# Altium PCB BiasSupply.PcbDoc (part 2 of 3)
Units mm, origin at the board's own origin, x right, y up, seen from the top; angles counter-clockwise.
Board outline 39 x 40.5 mm, 4 copper layers (Top Layer, Layer 2, Layer3, Bottom Layer), stack 0.661 mm thick; 168 components, 80 nets, 408 pads, 115 vias.
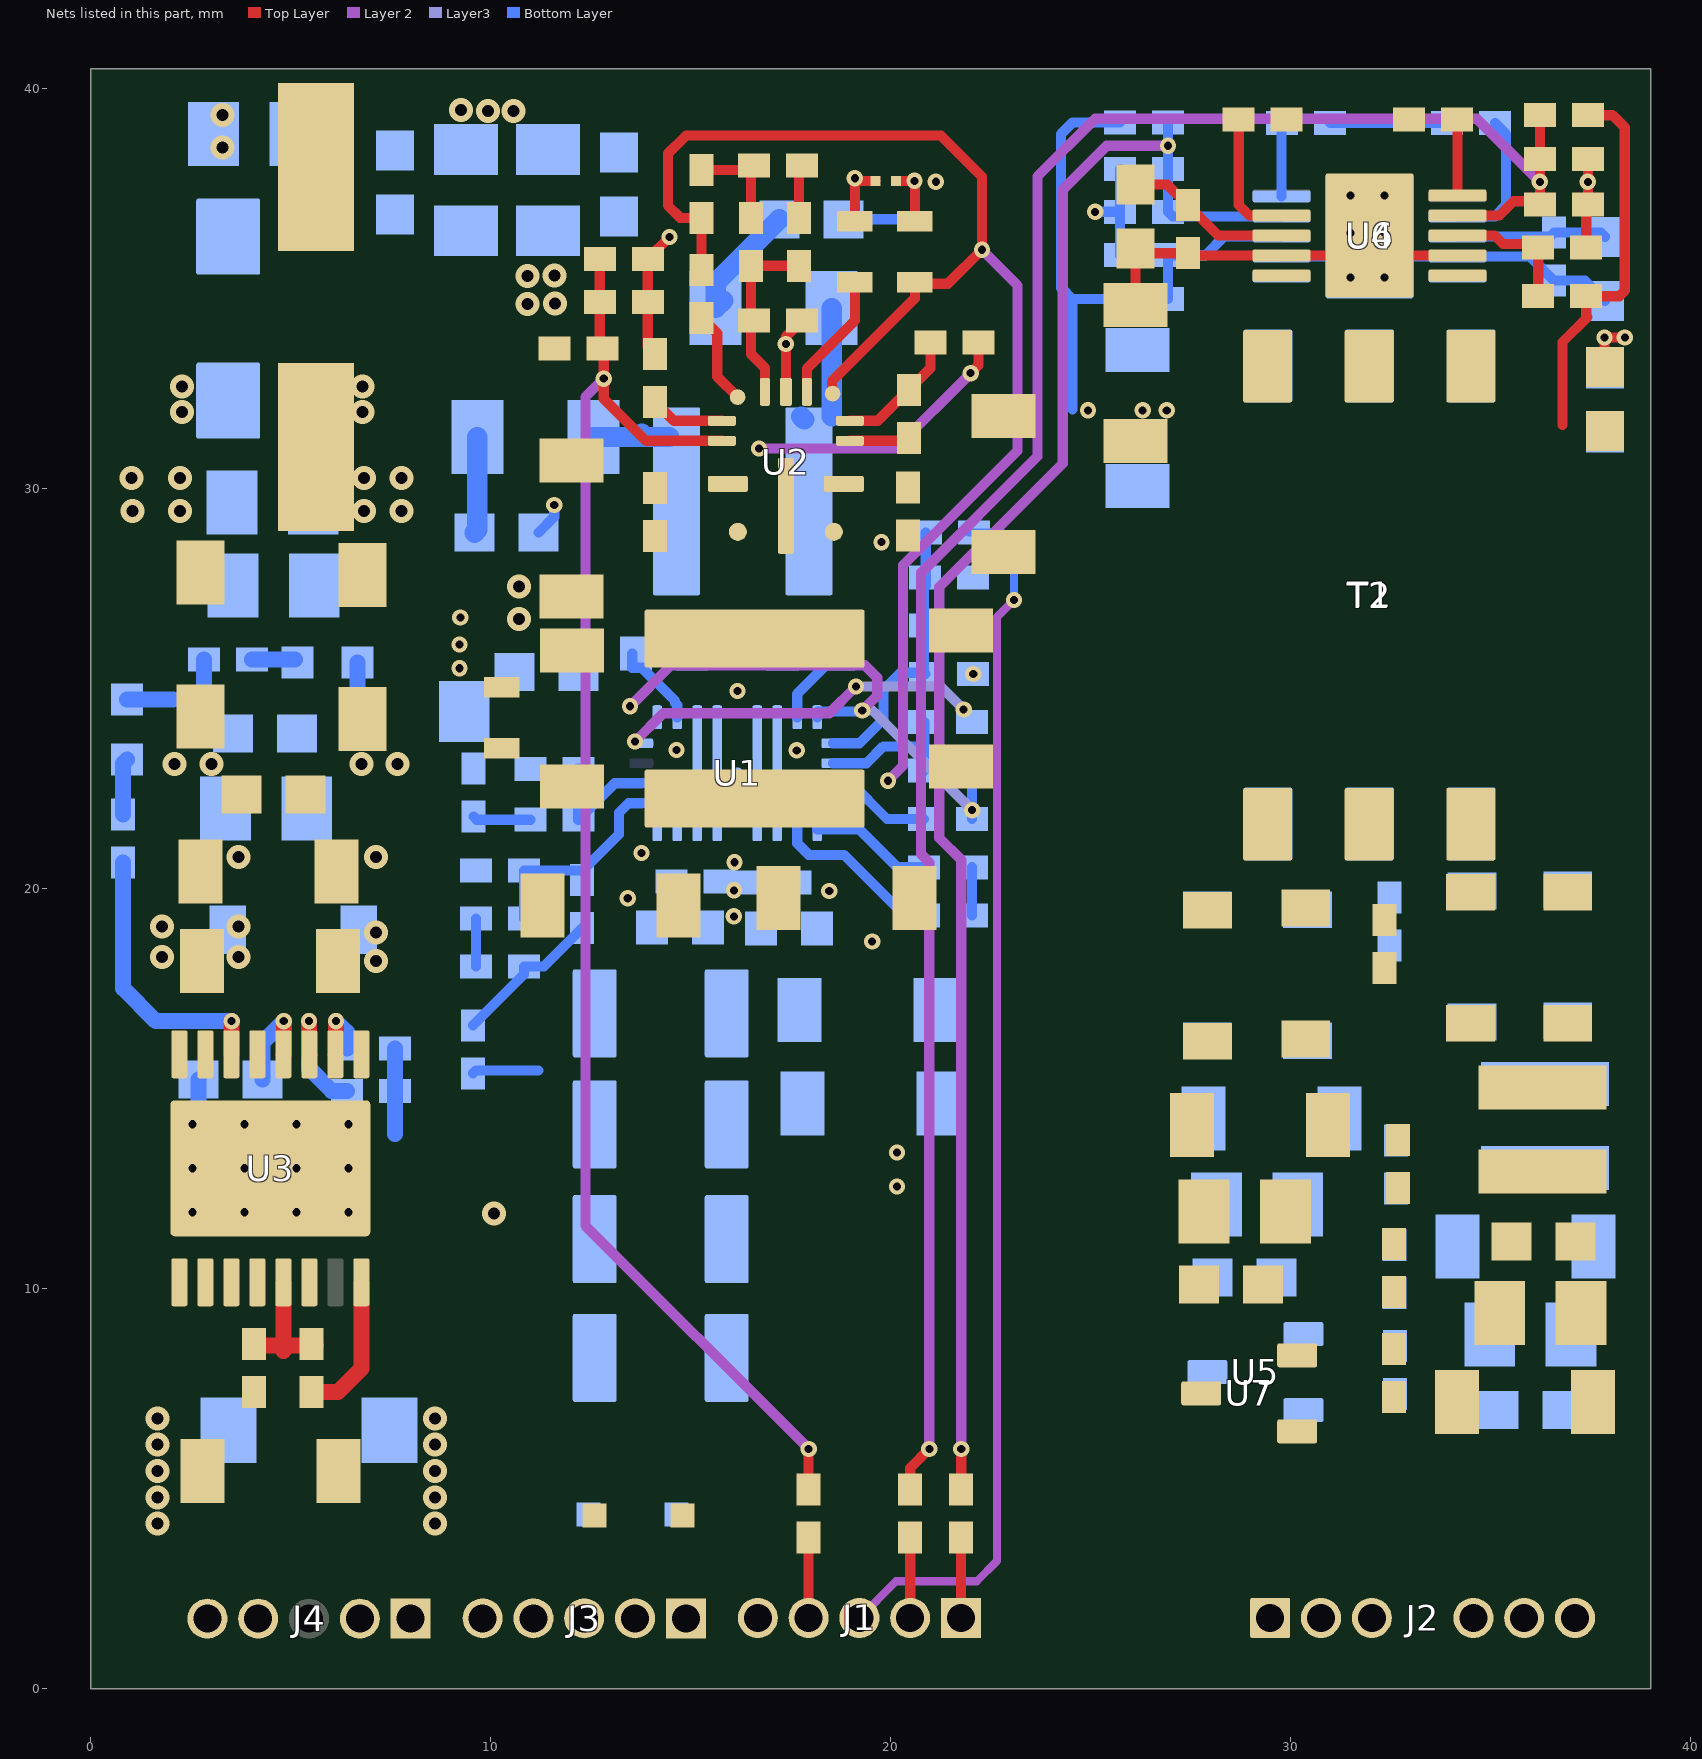
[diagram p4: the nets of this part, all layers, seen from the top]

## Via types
v1: diameter 0.406, hole 0.203, Top Layer to Bottom Layer, 57 vias
v2: diameter 0.6, hole 0.3, Top Layer to Bottom Layer, 46 vias
v3: diameter 0.5, hole 0.203, Top Layer to Bottom Layer, 6 vias
v4: diameter 0.5, hole 0.203, Top Layer to Bottom Layer, tented both sides, 6 vias

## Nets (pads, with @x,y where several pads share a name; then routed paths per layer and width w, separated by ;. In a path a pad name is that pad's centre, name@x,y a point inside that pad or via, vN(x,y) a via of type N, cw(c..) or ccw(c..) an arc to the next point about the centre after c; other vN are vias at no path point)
AGND1: C37.2 C48.2 NT2.2 R13.1 R17.1 R18.1 U2.3 | length 6.8
  Top Layer w0.254: R18.1@14.104,33.371 13.928,33.548 R17.1@13.928,34.671 C37.2@13.928,35.745 14.47,36.287 v1(14.47,36.295) ; U2.3@17.379,32.421 v1(17.379,33.615) 17.379,33.801 R13.1@17.784,34.206 ; C48.2@19.104,36.721 v1(19.104,37.759) 19.168,37.696 NT2.2@19.621,37.696
AGND2: C23.2 C24.2 C25.2 C59.2 NT1.1 R9.1 R11.1 R12.1 R26.1 U1.17 | length 10.2
  Layer 2 w0.254: v1(13.609,23.677) 14.317,24.386 18.467,24.386 v1(19.135,25.054)
  Layer3 w0.254: v1(19.135,25.054) 21.249,25.054 v1(21.825,24.478)
  Bottom Layer w0.254: R9.1@22.037,19.328 C24.2@22.037,20.535
BIAS_5V: C39.1 C40.2 C41.2 C47.1 C65.2 C66.2 D15.1 J3.1 L3.2 R19.1 R20.2 U2.1 | length 34.4
  Top Layer w0.254: R19.1@15.275,35.471 R20.2@15.275,36.771 14.74,36.771 14.43,37.081 14.43,38.373 14.882,38.825 21.257,38.825 22.282,37.8 v1(22.282,35.973) 21.43,35.121 20.604,35.121 20.604,34.759 18.529,32.684 U2.1@18.529,32.421
  Layer 2 w0.254: v1(19.935,22.698) 20.309,23.072 20.309,28.085 23.172,30.948 23.172,35.082 v1(22.282,35.973)
BIAS_12V: C13.1 C17.1 C18.1 C19.1 C20.1 C21.2 D1.1 J3.5 R3.2 U1.11 U1.12 U1.13 | length 1.7
  Bottom Layer w0.254: R3.2@9.559,15.385 9.632,15.458 11.198,15.458
  other v1: 13.427,19.76 13.771,20.891 14.646,23.469
BIAS_ISO_12V_1: C56.1 C57.1 C58.1 J2.3 L6.2 R36.2
BIAS_ISO_12V_2: C70.1 C71.1 C72.1 J2.7 L7.2 R49.2
BIAS_ISO_-5V_1: C44.2 C45.2 C67.2 D8.2 D9.2 J2.1 R46.1 U5.3
BIAS_ISO_-5V_2: C79.2 C80.2 C81.2 D12.2 D13.2 J2.5 R59.1 U7.3
BIAS_ISO_GND1: C44.1 C45.1 C56.2 C57.2 C58.2 C67.1 J2.2 R36.1 R37.2 R41.2 U5.1
BIAS_ISO_GND2: C70.2 C71.2 C72.2 C79.1 C80.1 C81.1 J2.6 R43.2 R49.1 R54.2 U7.1
BIAS_VIN: C3.1 C5.1 C6.2 C8.1 C15.1 C27.1 C28.1 C29.1 C30.1 C33.1 C34.1 C35.1 C36.1 C43.1 C64.1 C78.1 L2.2 R4.2 R14.2 R15.2 R35.2 R40.2 R45.2 R48.2 T1.2 T2.2 U1.7 U2.8 U2.12 | length 19.4
  Top Layer w0.254: 36.798,31.596 36.798,33.666 37.423,34.291 37.388,34.326 R40.2@37.388,34.812 38.214,34.812 38.354,34.952 38.354,39.032 38.049,39.337 R48.2@37.43,39.337
  Bottom Layer w0.254: 24.546,31.987 24.546,34.74 ; R35.2@25.732,34.74 24.546,34.74 ; R45.2@25.732,39.157 24.549,39.157 24.262,38.87 24.262,35.024 24.546,34.74
  other v1: 20.156,12.554 20.156,13.402 19.538,18.681 18.466,19.94 17.651,23.458 22.064,25.367 24.935,31.958 26.299,31.958 26.902,31.958
  other v2: 9.93,39.446 10.571,39.446 9.263,39.471
BIAS_VIN_EMI: C38.1 C51.1 C52.1 C53.1 C55.1 D2.1 D4.1 FB1.1 R27.2 U3.15 U3.16 | length 2.2
  Bottom Layer w0.4: D2.1@0.904,24.726 2.063,24.726 ; 2.832,24.698 R27.2@2.832,25.725
  other v2: 1.778,18.295 3.693,18.295 1.778,19.05 3.693,19.05 3.693,20.798 2.098,23.114 3.023,23.114
CBOOT_PIN: C46.1 R16.1 U2.14 | length 3.2
  Top Layer w0.254: U2.14@18.979,31.696 19.678,31.696 R16.1@20.453,32.471 20.993,33.011 C46.1@20.993,33.652
FB: C49.2 R13.2 R21.1 U2.4 | length 4.5
  Top Layer w0.254: U2.4@16.854,32.421 16.854,33.02 16.504,33.37 16.504,34.171 16.504,35.566 R21.1@16.509,35.571 C49.2@17.704,35.571
LM61440_EN: J1.4 R22.1 | length 2
  Top Layer w0.254: J1.4@17.949,1.768 R22.1@17.949,3.779
NetC1_1: C1.1 R1.2 | length 3.1
  Bottom Layer w0.508: R1.2@15.811,34.704 R1.2@15.625,34.519 15.625,35.142 C1.1@17.218,36.735
NetC2_1: C2.1 R2.1 | length 2.4
  Bottom Layer w0.508: C2.1@9.596,28.902 9.667,28.974 R2.1@9.667,31.294
NetC4_1: C4.1 R53.2 U4.8 | length 3.8
  Bottom Layer w0.254: U4.8@34.173,36.308 36.491,36.308 R53.2@36.583,36.4 37.751,36.4 C4.1@37.854,36.297
NetC7_1: C7.1 R68.2 U6.8 | length 4.2
  Top Layer w0.254: C7.1@26.124,37.601 26.917,37.601 R68.2@27.432,37.086 28.188,36.33 U6.8@29.773,36.33
NetC9_2: C9.2 R35.1 U4.3 | length 4.1
  Bottom Layer w0.254: R35.1@26.932,34.74 C9.2@26.932,35.837 27.871,35.837 28.341,36.308 U4.3@29.773,36.308
NetC10_1: C10.1 L1.1 R1.1 U1.8 | length 2.8
  Bottom Layer w0.508: L1.1@17.763,31.802 L1.1@17.838,31.728 ; L1.1@18.525,31.802 R1.1@18.525,34.519
NetC10_2: C10.2 U1.20 | length 2
  Bottom Layer w0.254: U1.20@17.665,24.286 17.665,24.871 C10.2@18.679,25.885
NetC12_1: C12.1 L1.2 R2.2 U1.10 | length 2
  Bottom Layer w0.508: R2.2@12.567,31.294 13.699,31.294 ; 13.78,31.375 13.699,31.294 ; L1.2@14.461,31.294 13.699,31.294
NetC12_2: C12.2 U1.19 | length 2.2
  Bottom Layer w0.254: C12.2@13.538,25.878 13.538,25.524 13.78,25.524 14.612,24.692 14.612,24.639 14.665,24.586 U1.19@14.665,24.286
NetC14_1: C14.1 R45.1 R47.2 R56.2 U4.4 | length 42.1
  Top Layer w0.254: R56.2@21.759,4.979 21.764,4.984 v1@21.764,5.887
  Layer 2 w0.254: v1(21.764,5.995) 21.764,20.719 21.217,21.267 21.217,27.544 24.304,30.631 24.304,37.476 25.4,38.572 v1(26.932,38.572)
  Bottom Layer w0.254: R45.1@26.932,39.157 v1(26.932,38.572) R47.2@26.932,37.987 C14.1@26.932,36.921 27.045,36.808 U4.4@29.773,36.808
NetC16_2: C16.2 R40.1 U6.3 | length 3.6
  Top Layer w0.254: U6.3@34.173,36.33 35.099,36.33 35.314,36.116 C16.2@36.442,36.116 ; R40.1@36.188,34.812 C16.2@36.188,36.031
NetC23_1: C23.1 R6.2 U1.15 | length 3.2
  Bottom Layer w0.254: C23.1@12.19,22.997 R6.2@12.19,21.723 13.103,22.636 U1.15@13.765,22.636
NetC24_1: C24.1 U1.5 | length 3.1
  Bottom Layer w0.254: U1.5@18.165,21.486 19.215,21.486 20.166,20.535 C24.1@20.837,20.535
NetC25_1: C25.1 R6.1 | length 1.5
  Bottom Layer w0.254: C25.1@9.57,21.807 9.654,21.723 R6.1@10.99,21.723
NetC26_1: C26.1 R7.1 | length 1.2
  Bottom Layer w0.254: R7.1@9.632,18.056 C26.1@9.632,19.255
NetC26_2: C26.2 R8.1 R12.2 U1.14 | length 5.1
  Bottom Layer w0.254: C26.2@10.832,19.255 R12.2@10.832,20.454 12.304,20.454 13.208,21.358 13.208,21.899 13.444,22.136 U1.14@13.765,22.136
NetC31_1: C31.1 C32.1 FB1.2 L2.1
  other v2: 1.041,29.442 2.231,29.442 1.019,30.27 2.231,30.27 2.286,31.915 2.286,32.56
NetC37_1: C37.1 R15.1 R17.2 R22.2 U2.7 | length 37
  Top Layer w0.254: C37.1@12.728,35.595 R17.2@12.728,34.671 12.728,33.565 R15.1@12.793,33.5 ; R15.1@12.828,33.465 v1(12.828,32.75) 12.828,32.247 13.879,31.196 U2.7@15.779,31.196 ; R22.2@17.949,4.979 v1(17.949,5.995)
  Layer 2 w0.254: v1(12.828,32.75) 12.368,32.29 12.368,11.576 v1(17.949,5.995)
NetC42_1: C42.1 R48.1 R50.2 R57.2 U6.4 | length 52.6
  Top Layer w0.254: R57.2@20.489,4.979 20.489,5.517 v1(20.966,5.995) ; U6.4@34.173,36.83 35.217,36.83 35.573,37.186 36.145,37.186 C42.1@36.23,37.101 v1(36.23,37.67) R50.2@36.23,38.24 R48.1@36.23,39.337
  Layer 2 w0.254: v1(20.966,5.995) 20.966,20.655 20.763,20.858 20.763,27.897 23.673,30.807 23.673,37.807 25.113,39.247 34.653,39.247 v1(36.23,37.67)
NetC49_1: C49.1 R23.2 | length 1.3
  Top Layer w0.254: C49.1@17.704,36.771 17.704,38.019 R23.2@17.741,38.056
NetC54_1: C54.1 U3.12 | length 2.5
  Top Layer w0.4: U3.12@4.817,15.86 4.828,15.871 v1(4.828,16.688)
  Bottom Layer w0.4: C54.1@4.3,15.228 4.3,16.16 v1(4.828,16.688)
NetC59_1: C59.1 R4.1 R5.2 R11.2 U1.1 | length 7
  Bottom Layer w0.254: U1.1@18.565,23.636 19.221,23.636 19.821,24.236 19.821,24.973 20.245,25.397 20.834,25.397 R4.1@20.837,25.393 ; R4.1@20.864,25.367 R4.1@20.837,25.393 ; R5.2@20.879,28.902 20.879,27.569 20.837,27.527 R4.1@20.837,25.393
NetC63_1: C63.1 R14.1
  other v2: 3.302,38.525 3.302,39.347
NetD2_2: D2.2 R24.1 | length 1.4
  Bottom Layer w0.4: R24.1@0.809,21.853 0.809,23.131 D2.2@0.904,23.226
NetD5_1: D5.1 R27.1 | length 1.1
  Bottom Layer w0.4: R27.1@4.032,25.725 D5.1@5.105,25.725
NetD6_1: D6.1 D7.1 L6.1
NetD10_1: D10.1 D11.1 L7.1
NetD10_2: D10.2 D12.1 T2.6
NetD11_2: D11.2 D13.1 T2.4
NetR3_1: R3.1 R7.2 R8.2 | length 3.8
  Bottom Layer w0.254: R3.1@9.559,16.585 10.832,17.859 R7.2@10.832,18.056 11.327,18.056 R8.2@12.285,19.014
NetR9_2: R9.2 U1.6 | length 4.3
  Bottom Layer w0.254: U1.6@17.665,21.486 17.665,21.133 17.953,20.845 18.831,20.845 20.348,19.328 R9.2@20.837,19.328
NetR10_2: R10.2 U1.3 | length 2.6
  Bottom Layer w0.254: U1.3@18.565,22.636 19.014,22.636 19.908,21.742 R10.2@20.837,21.742
NetR20_1: R20.1 R21.2 R23.1 | length 2.4
  Top Layer w0.254: R20.1@15.275,37.971 16.456,37.971 16.509,37.917 R21.2@16.509,36.771
NetR24_2: R24.2 U3.14 | length 7
  Top Layer w0.4: U3.14@3.517,15.86 3.524,15.867 v1(3.524,16.688)
  Bottom Layer w0.4: R24.2@0.809,20.653 0.809,17.507 1.628,16.688 v1(3.524,16.688)
NetR25_1: R25.1 R26.2 U1.2 | length 3.7
  Bottom Layer w0.254: U1.2@18.565,23.136 19.395,23.136 19.817,23.557 20.837,23.557 ; R25.1@20.837,22.949 20.837,23.557 ; R26.2@20.839,24.168 20.839,23.559 20.837,23.557
NetR33_2: R33.2 U3.10 | length 1.6
  Top Layer w0.4: U3.10@6.117,15.86 6.131,15.874 v1(6.131,16.688)
  Bottom Layer w0.4: v1(6.131,16.688) 6.408,16.41 R33.2@6.408,16.002
NetR34_2: R34.2 U3.11 | length 3.2
  Top Layer w0.4: v1(5.461,16.688) 5.461,15.866 U3.11@5.467,15.86
  Bottom Layer w0.4: v1(5.461,16.688) v1(5.461,16.688) 5.46,15.507 6.021,14.945 R34.2@6.406,14.945
NetR39_2: R39.2 U4.7 | length 3.5
  Bottom Layer w0.254: U4.7@34.173,36.808 35.107,36.808 35.381,37.082 35.381,38.87 R39.2@35.113,39.138
NetR41_1: R41.1 R46.2 U5.2
NetR42_2: R42.2 U4.5 | length 1.8
  Bottom Layer w0.254: U4.5@29.773,37.308 29.773,39.123 R42.2@29.788,39.138
NetR43_1: R43.1 T2.5
NetR52_2: R52.2 U6.7 | length 3.3
  Top Layer w0.254: R52.2@28.702,39.232 28.702,37.093 28.964,36.83 U6.7@29.773,36.83
NetR54_1: R54.1 R59.2 U7.2
NetR55_2: R55.2 U6.5 | length 1.9
  Top Layer w0.254: R55.2@34.162,39.232 34.173,39.221 U6.5@34.173,37.33
NetT2_1: T2.1 U6.1
NetT2_3: T2.3 U6.10
OUT_OVP: R28.1 R32.2 U3.5 | length 3
  Top Layer w0.4: R28.1@4.381,8.583 4.817,8.583 ; 4.817,8.446 4.817,8.583 ; U3.5@4.817,10.16 4.817,8.583 ; R32.2@5.637,8.583 4.817,8.583
PGND: C1.2 C2.2 C3.2 C4.2 C5.2 C6.1 C7.2 C8.2 C9.1 C11.2 C13.2 C14.2 C15.2 C16.1 C17.2 C18.2 C19.2 C20.2 C21.1 C27.2 C28.2 C29.2 C30.2 C31.2 C32.2 C33.2 C34.2 C35.2 C36.2 C39.2 C40.1 C41.1 C42.2 C43.2 C47.2 C63.2 C64.2 C65.1 C66.1 C78.2 D1.2 D15.2 FB2.2 J1.5 J3.2 J3.3 J3.4 NT1.2 NT2.1 R39.1 R42.1 R47.1 R50.1 R52.1 R53.1 R55.1 R68.1 U1.9 U2.9 U2.11 U4.2 U4.9 U4.11 U6.2 U6.9 U6.11 | length 31.9
  Top Layer w0.254: NT2.1@20.129,37.696 v1(20.593,37.696) 20.604,37.684 C47.2@20.604,36.721 ; C43.2@26.124,34.588 26.124,35.772 26.239,35.886 R68.1@27.432,35.886 27.488,35.83 U6.9@29.773,35.83 31.473,35.83 U6.11@31.973,36.33 32.473,35.83 U6.2@34.173,35.83 ; C16.1@37.388,36.031 37.388,37.059 C42.2@37.43,37.101 R50.1@37.43,38.24 ; C78.2@37.854,33.046 37.846,33.054 v1(37.846,33.782) v1(38.354,33.782)
  Bottom Layer w0.254: C2.2@11.196,28.902 11.589,29.295 v1(11.589,29.593) ; C1.2@18.818,36.735 20.604,36.735 ; v1(25.113,36.921) C14.2@25.732,36.921 ; C9.1@25.732,35.837 C14.2@25.732,36.921 ; R47.1@25.732,37.987 C14.2@25.732,36.921 ; U4.2@29.773,35.808 31.473,35.808 U4.11@31.973,36.308 32.473,35.808 U4.9@34.173,35.808 35.975,35.808 R53.1@36.583,35.2 37.351,35.2 C4.2@37.854,34.697 ; R42.1@30.988,39.138 R39.1@33.913,39.138
  other v1: 16.079,19.308 16.082,19.959 16.096,20.662 16.17,24.942 9.219,25.51 9.22,26.103 9.241,26.777 19.771,28.663 31.496,35.278 32.342,35.278 31.496,36.387 32.342,36.387 31.496,37.33 32.342,37.33 21.13,37.673 37.43,37.67
  other v2: 10.081,11.885 10.703,26.742 10.707,27.558 6.829,29.442 7.77,29.442 6.829,30.27 7.77,30.27 6.798,31.915 6.798,32.56 10.915,34.619 11.604,34.629 10.915,35.319 11.593,35.33
PGND1: C38.2 C50.2 C51.2 C52.2 C53.2 C55.2 D3.1 D4.2 D5.2 FB2.1 J4.1 J4.2 U3.9 | length 0.9
  Bottom Layer w0.4: 6.676,24.729 D5.2@6.676,25.654
  other v2: 8.611,4.126 8.611,4.783 8.611,5.441 8.611,6.099 8.611,6.756 7.136,18.189 7.128,18.905 7.128,20.798 6.767,23.114 7.671,23.114
RBOOT_PIN: R16.2 U2.13 | length 1.5
  Top Layer w0.254: U2.13@18.979,31.196 20.378,31.196 R16.2@20.453,31.271
RESET_PIN: R19.2 U2.5 | length 2.4
  Top Layer w0.254: R19.2@15.275,34.271 15.663,33.882 15.663,32.8 U2.5@16.173,32.29
RT_MODE: R18.2 U2.6 | length 1.9
  Top Layer w0.254: R18.2@14.104,32.171 14.579,31.696 U2.6@15.779,31.696
RTN1: C54.2 R32.1 R33.1 R34.1 U3.4 U3.6 U3.8 U3.13 U3.17@4.492,13.01 | length 7
  Top Layer w0.4: R32.1@5.519,7.422 6.189,7.422 6.767,8.001 U3.8@6.767,10.16
  Bottom Layer w0.4: v4(2.542,14.11) 2.7,14.268 C54.2@2.7,15.228 ; 7.606,13.861 R34.1@7.606,14.945 7.608,14.947 R33.1@7.608,16.002
  other v3: 3.842,11.91 5.142,11.91 3.842,13.01 5.142,13.01 3.842,14.11 5.142,14.11
  other v4: 2.542,11.91 6.442,11.91 2.542,13.01 6.442,13.01 6.442,14.11
SN6507_EN1: J1.1 R56.1 | length 2
  Top Layer w0.254: J1.1@21.759,1.768 R56.1@21.759,3.779
  Bottom Layer w0.254: J1.1@21.759,1.768 J1.1@21.778,1.787
SN6507_EN2: J1.2 R57.1 | length 2
  Top Layer w0.254: J1.2@20.489,1.768 R57.1@20.489,3.779
SW_PIN: C46.2 L3.1 U2.10 | length 6.9
  Top Layer w0.254: v1(22,32.888) 22.193,33.081 C46.2@22.193,33.652
  Layer 2 w0.254: v1(16.71,31.005) 20.117,31.005 v1(22,32.888)
TPS552872_EN: J1.3 R5.1 | length 30.9
  Layer 2 w0.203: J1.3@19.219,1.768 20.137,2.686 22.153,2.686 22.657,3.19 22.657,26.79 v1(23.081,27.215)
  Bottom Layer w0.203: R5.1@21.952,28.902 22.775,28.902 23.081,28.596 v1(23.081,27.215)
VBAT: C50.1 D3.2 J4.4 J4.5 R28.2 U3.1 U3.2 U3.3
  other v2: 1.676,4.126 1.676,4.783 1.676,5.441 1.676,6.099 1.676,6.756
VCC: C11.1 R10.1 R25.2 U1.18 U1.21 | length 14
  Layer 2 w0.254: v1(13.486,24.56) 14.51,25.584 19.354,25.584 19.665,25.273 19.665,24.834 19.62,24.79 19.62,24.785 v1(19.291,24.455)
  Layer3 w0.254: v1(19.291,24.455) 19.544,24.455 v1(22.037,21.962)
  Bottom Layer w0.254: U1.21@18.165,24.286 18.165,24.419 18.172,24.426 19.261,24.426 v1(19.291,24.455) ; R10.1@22.037,21.742 v1(22.037,21.962) R25.2@22.037,22.949
VCC_PIN: C48.1 U2.2 | length 3.2
  Top Layer w0.254: U2.2@17.904,32.421 17.904,33 19.104,34.2 C48.1@19.104,35.121
XP1: T1.1 U4.1
XP3: T1.3 U4.10
XP4: D7.2 D9.1 T1.4
XP5: R37.1 T1.5
XP6: D6.2 D8.1 T1.6
pads on no net: J4.3 LBL1.0 U1.4 U1.16 U3.7 U3.17@4.492,13.01 U4.6 U6.6

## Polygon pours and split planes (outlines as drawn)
PGND1 on Top Layer "TOP_LAYER_PGND1_P004" (solid, remove dead copper, pour order 4): 4.826,24.732 5.086,24.992 8.671,24.992 8.949,24.714 8.949,3.925 8.58,3.556 5.644,3.556 5.254,3.947 5.254,7.253 5.855,7.854 6.791,7.854 7.113,8.176 7.113,14.494 6.487,15.12 6.487,16.084 4.826,17.744
BIAS_ISO_-5V_2 on Top Layer "TOP_LAYER_BIAS_ISO_-5V_2_P368" (solid, pour order 368): 26.979,5.255 27.483,4.751 33.214,4.751 34.029,3.937 34.029,1.709 34.301,1.436 34.793,1.436 34.793,1.479 35.075,1.76 35.075,4.751 34.156,5.671 28.878,5.671 28.534,6.014 28.534,6.81 28.736,7.011 30.954,7.011 31.118,6.848 32.979,6.848 33.1,6.969 33.1,7.4 32.846,7.654 28.712,7.654 28.456,7.91 28.456,14.923 29.273,15.74 30.972,15.74 31.074,15.841 31.074,17.129 30.976,17.226 27.339,17.226 26.979,16.867
NetD11_2 on Top Layer "TOP_LAYER_NETD11_2_P365" (solid, pour order 365): 35.776,19.022 36.034,18.764 37.242,18.764 37.751,19.273 37.751,23.148 36.317,24.582 29.282,24.582 27.29,22.59 27.29,18.63 27.461,18.459 28.347,18.459 28.967,19.078 28.967,19.664 29.962,20.659 29.962,23.026 30.816,23.88 34.804,23.88 35.776,22.908
BIAS_ISO_GND2 on Top Layer "TOP_LAYER_BIAS_ISO_GND2_P369" (solid, pour order 369): 33.1,6.569 33.465,6.935 33.465,10.502 33.277,10.69 31.776,10.69 31.512,10.427 31.512,9.382 31.215,9.084 29.015,9.084 28.795,9.304 28.795,13.54 30.545,15.29 31.117,15.29 31.512,15.686 31.512,19.658 31.858,20.003 32.914,20.003 33.209,19.708 33.209,15.421 32.486,14.698 31.746,13.958 31.746,13.369 32.166,12.949 33.649,12.949 34.83,11.767 35.855,11.767 36.342,11.28 36.342,1.714 35.991,1.363 35.776,1.363 35.776,1.374 35.316,1.833 35.316,4.983 34.364,5.936 29.837,5.936 29.687,6.086 29.687,6.619 29.79,6.722 30.59,6.722 30.743,6.569
NetR54_1 on Top Layer "TOP_LAYER_NETR54_1_P372" (solid, pour order 372): 32.821,7.996 33.12,8.295 33.12,10.128 32.94,10.309 32.265,10.309 32.059,10.102 32.059,9.318 31.395,8.654 29.687,8.654 29.687,7.996
BIAS_ISO_12V_2 on Top Layer "TOP_LAYER_BIAS_ISO_12V_2_P371" (solid, pour order 371): 37.984,1.258 38.368,1.642 38.368,13.271 38.06,13.58 34.808,13.58 34.127,14.261 32.37,14.261 32.125,14.016 32.125,13.505 32.272,13.357 33.763,13.357 35.038,12.083 36.104,12.083 36.599,11.588 36.599,1.475 36.816,1.258
NetD10_1 on Top Layer "TOP_LAYER_NETD10_1_P370" (solid, pour order 370): 37.953,14.433 38.354,14.835 38.354,17.551 33.648,17.551 33.648,15.454 34.669,14.433
NetD10_2 on Top Layer "TOP_LAYER_NETD10_2_P367" (solid, pour order 367): 33.74,18.764 33.775,18.798 35.075,18.798 35.148,18.871 35.148,22.706 34.268,23.586 30.897,23.586 30.301,22.99 30.301,20.326 29.862,19.886 29.862,18.42 31.077,18.42 31.077,22.52 31.345,22.789 33.497,22.789 33.74,22.546
NetR43_1 on Top Layer "TOP_LAYER_NETR43_1_P366" (solid, pour order 366): 31.395,21.987 31.547,22.14 32.825,22.14 33.069,21.896 33.069,18.812 31.851,18.812 31.395,19.268 31.395,20.358
PGND on Top Layer "TOP_LAYER_PGND_P359" (solid, pour order 359): 25.124,33.159 25.153,33.131 27.692,33.131 27.692,35.267 27.681,35.278 25.198,35.278 25.124,35.204
NetT2_1 on Top Layer "TOP_LAYER_NETT2_1_P357" (solid, pour order 357): 33.497,35.459 33.497,31.92 33.711,31.706 35.099,31.706 35.217,31.824 35.217,35.341 35.099,35.459
NetT2_3 on Top Layer "TOP_LAYER_NETT2_3_P356" (solid, pour order 356): 28.989,35.459 28.702,35.172 28.702,31.706 30.068,31.706 30.496,32.134 30.496,35.397 30.423,35.471 30.411,35.459
PGND on Top Layer "TOP_LAYER_PGND_P355" (solid, pour order 355): 33.452,39.643 33.237,39.859 33.16,39.858 29.616,39.858 29.402,39.643 29.402,38.825 30.734,37.493 30.734,34.405 33.188,34.405 33.188,37.371 33.452,37.635
PGND on Top Layer "TOP_LAYER_PGND_P307" (solid, pour order 307): 23.959,27.301 23.959,29.213 18.401,29.213 18.23,29.042 18.23,28.126 20.374,28.126 20.5,28 20.5,25.323 20.76,25.063 22.695,25.063 22.82,25.177 22.82,26.162
PGND on Top Layer "TOP_LAYER_PGND_P271" (solid, remove dead copper, pour order 271): 13.208,20.828 13.678,20.358 14.43,20.358 14.9,20.828 21.596,20.828 22.787,19.636 22.787,2.894 20.904,1.01 9.398,1.01 9.398,19.888 10.338,20.828
NetC63_1 on Top Layer "TOP_LAYER_NETC63_1_P269" (solid, remove dead copper, pour order 269): 4.94,35.56 6.386,35.56 6.617,35.791 6.617,39.643 6.377,39.884 2.583,39.884 2.337,39.637 2.337,38.163
PGND on Top Layer "TOP_LAYER_PGND_P267" (solid, remove dead copper, pour order 267): 4.817,26.958 5.105,26.67 7.877,26.67 8.226,27.004 8.226,33.415 7.806,33.836 5.132,33.836 5.109,33.859 4.817,33.567
NetC31_1 on Top Layer "TOP_LAYER_NETC31_1_P265" (solid, remove dead copper, pour order 265): 0.507,27.178 1.015,26.67 1.067,26.67 3.827,26.67 4.081,26.924 4.081,28.292 4.081,33.524 3.585,34.021 0.866,34.021 0.495,33.65
BIAS_VIN_EMI on Top Layer "TOP_LAYER_BIAS_VIN_EMI_P261" (solid, remove dead copper, pour order 261): 2.888,15.103 3.106,15.328 3.106,15.892 3.106,16.68 4.3,17.874 4.3,24.555 3.863,24.992 0.811,24.992 0.508,24.689 0.508,15.458 0.862,15.105 1.524,15.102
RTN1 on Top Layer "TOP_LAYER_RTN1_P259" (solid, remove dead copper, pour order 259): 0.804,14.831 3.252,14.831 3.903,15.494 6.191,15.494 7.042,14.643 7.042,9.722 6.973,9.652 2.54,9.652 0.779,11.159 0.5,11.439 0.5,14.527
BIAS_VIN on Top Layer "TOP_LAYER_BIAS_VIN_P192" (solid, pour order 192): 24.895,32.631 23.959,33.567 23.058,33.567 21.185,31.695 21.185,30.795 20.989,30.599 18.427,30.599 18.299,30.444 18.299,29.809 18.482,29.625 37.968,29.625 38.545,30.202 38.545,31.824 38.449,31.92 36.813,31.92 36.164,31.271 33.07,31.271 32.632,31.71 32.632,33.555 32.449,33.737 31.431,33.737 31.242,33.548 31.242,31.624 30.854,31.236 28.162,31.236 26.767,32.631
BIAS_5V on Top Layer "TOP_LAYER_BIAS_5V_P040" (solid, remove dead copper, pour order 40): 19.235,18.798 18.732,18.295 18.732,7.886 18.355,7.509 16.921,7.509 15.779,6.368 15.779,1.763 15.191,1.175 14.348,1.175 13.97,1.552 13.97,2.16 13.863,2.267 13.863,20.823 13.472,21.214 10.049,21.214 9.696,21.547 9.696,23.35 10.096,23.75 21.371,23.75 22.509,23.75 22.812,23.447 22.82,23.312 22.82,21.59 22.82,21.577 22.3,21.057 20.269,21.057 19.525,20.313 19.525,19.088
PGND on Top Layer "TOP_LAYER_PGND_P032" (solid, remove dead copper, pour order 32): 12.713,24.5 13.113,24.932 13.113,27.417 13.392,27.696 16,27.696 16.5,27.696 16.5,29.145 16.364,29.281 10.745,29.281 9.627,28.163 9.627,24.955 10.081,24.5
SW_PIN on Top Layer "TOP_LAYER_SW_PIN_P034" (solid, remove dead copper, pour order 34): 16.791,30.64 16.504,30.927 16.504,31.278 16.656,31.43 17.83,31.43 17.904,31.356 17.904,27.83 18.259,27.475 19.151,27.475 19.671,26.955 19.671,25.177 19.378,24.884 14.071,24.884 13.855,25.1 13.855,26.981 14.21,27.336 16.361,27.336 16.791,27.766
BIAS_VIN on Top Layer "TOP_LAYER_BIAS_VIN_P030" (solid, remove dead copper, pour order 30): 8.949,39.675 9.406,40.132 9.424,40.132 23.266,40.132 24.427,38.971 24.427,32.004 22.211,32.004 21.919,32.297 22.82,33.199 22.82,37.955 21.743,39.032 12.893,39.032 12.03,38.169 12.03,34.583 12.03,32.388 13.866,30.551 16.399,30.551 16.504,30.446 16.504,29.891 16.183,29.575 13.381,29.575 9.823,29.575 8.949,30.449
VBAT on Top Layer "TOP_LAYER_VBAT_P002" (solid, remove dead copper, pour order 2): 0.5,7.65 0.5,10.66 0.762,10.922 3.699,10.922 3.81,10.811 3.81,7.955 4.604,7.955 4.817,7.742 4.817,3.934 4.44,3.556 0.907,3.556 0.5,3.963
AGND2 on Bottom Layer "BOTTOM_LAYER_AGND2_P392" (solid, remove dead copper, pour order 392): 21.613,18.829 22.389,18.829 23.119,19.559 23.119,19.814 23.119,24.869 23.119,27.774 22.671,28.221 21.776,28.221 21.544,27.989 21.544,23.818 21.88,23.482 22.059,23.482 22.657,22.885 22.657,21.826 21.613,20.782
BIAS_VIN on Bottom Layer "BOTTOM_LAYER_BIAS_VIN_P387" (solid, remove dead copper, pour order 387): 17.39,24.578 17.39,24.137 17.919,23.608 17.919,22.194 17.724,21.998 17.724,21.073 18.344,20.454 18.919,20.454 22.191,17.182 22.191,12.337 21.764,11.91 19.665,11.91 19.477,12.099 19.477,17.007 17.724,18.759 17.724,19.146 17.009,19.861 17.009,24.442 17.144,24.578
PGND on Bottom Layer "BOTTOM_LAYER_PGND_P389" (solid, remove dead copper, pour order 389): 16.105,25.614 16,25.509 16,21.12 15.432,20.552 15.432,19.991 15.437,19.986 15.021,19.571 15.021,17.454 14.821,17.255 14.821,6.709 15.432,6.099 17.092,6.099 18.865,7.872 18.865,17.058 17.393,18.529 17.393,19.197 16.838,19.752 16.838,20.677 16.499,21.017 16.376,21.017 16.33,21.063 16.33,25.494 16.21,25.614
NetC10_1 on Bottom Layer "BOTTOM_LAYER_NETC10_1_P384" (solid, remove dead copper, pour order 384): 16.777,21.207 16.762,24.659 17.009,24.906 17.413,24.906 17.709,25.202 17.709,25.867 19.041,27.2 19.041,32.198 18.715,32.525 17.649,32.525 17.328,32.203 17.328,27.48 16.51,26.662 16.51,21.25 16.566,21.193 16.763,21.193
NetC12_1 on Bottom Layer "BOTTOM_LAYER_NETC12_1_P383" (solid, remove dead copper, pour order 383): 15.785,21.236 15.785,26.619 15.559,26.845 15.559,32.13 15.165,32.525 13.755,32.525 13.561,32.331 13.561,27.188 14.646,26.103 14.646,25.287 15.079,24.854 15.327,24.854 15.545,24.636 15.545,21.236
PGND on Bottom Layer "BOTTOM_LAYER_PGND_P395" (solid, remove dead copper, pour order 395): 8.859,27.064 9.525,27.064 10.02,26.569 10.311,26.569 11.069,25.812 11.069,24.982 10.915,24.828 8.86,24.828 8.543,25.146 8.543,26.748
BIAS_12V on Bottom Layer "BOTTOM_LAYER_BIAS_12V_P388" (solid, remove dead copper, pour order 388): 15.289,24.556 15.273,24.571 15.127,24.571 15.127,24.48 15.033,24.386 15.033,24.168 14.409,23.545 14.409,22.078 12.917,20.586 12.917,18.72 10.99,16.793 10.99,4.487 9.049,2.546 9.049,1.184 9.218,1.016 10.278,1.016 10.428,1.167 10.428,2.203 11.085,2.86 12.19,2.86 13.077,3.746 13.077,5.134 14.461,6.519 14.461,17.35 14.78,17.67 14.78,19.802 15.289,20.311
AGND2 on Bottom Layer "BOTTOM_LAYER_AGND2_P386" (solid, remove dead copper, pour order 386): 14.073,23.517 14.073,23.88 13.648,23.88 12.69,23.88 12.114,24.455 8.658,24.455 8.589,24.386 8.589,20.358 9.013,19.933 9.88,19.933 11.397,21.45 11.397,23.517
VCC on Bottom Layer "BOTTOM_LAYER_VCC_P385" (solid, remove dead copper, pour order 385): 15.033,24.086 15.033,24.386 14.689,24.729 14.073,24.729 12.917,25.885 11.862,25.885 11.702,25.725 11.702,25.18 12.797,24.086 14.866,24.086
PGND on Bottom Layer "BOTTOM_LAYER_PGND_P360" (solid, pour order 360): 33.045,34.383 33.293,34.632 33.293,37.468 34.145,38.32 34.173,38.32 34.173,40.132 21.352,40.132 20.302,39.082 20.302,34.892 20.811,34.383 21.766,34.383 23.491,32.658 27.856,32.658 28.364,33.166 28.364,35.253 28.779,35.668 30.593,35.668 30.734,35.527 30.734,34.602 30.953,34.383
BIAS_ISO_-5V_1 on Bottom Layer "BOTTOM_LAYER_BIAS_ISO_-5V_1_P376" (solid, pour order 376): 28.511,1.557 28.517,1.563 28.517,4.413 26.979,5.951 26.979,16.867 27.339,17.226 30.976,17.226 31.133,17.07 31.133,15.9 30.972,15.74 29.273,15.74 28.702,15.168 28.702,6.631 29.001,6.332 30.908,6.332 32.355,7.779 32.907,7.779 32.907,6.933 29.97,3.996 29.97,1.477 29.751,1.258 28.81,1.258
XP5 on Bottom Layer "BOTTOM_LAYER_XP5_P375" (solid, pour order 375): 31.356,19.814 31.854,19.316 32.817,19.316 33.082,19.581 33.082,21.883 32.587,22.378 31.535,22.378 31.356,22.198
NetD6_1 on Bottom Layer "BOTTOM_LAYER_NETD6_1_P380" (solid, pour order 380): 33.812,15.29 34.547,14.555 37.953,14.555 38.356,14.958 38.356,17.35 37.941,17.765 34.098,17.765 33.812,17.479
BIAS_ISO_12V_1 on Bottom Layer "BOTTOM_LAYER_BIAS_ISO_12V_1_P379" (solid, pour order 379): 32.21,13.42 32.272,13.42 32.435,13.257 33.969,13.257 34.932,12.294 35.067,12.294 36.313,11.049 36.313,6.496 34.952,5.135 33.309,5.135 31.542,3.367 31.542,1.529 31.803,1.268 32.322,1.268 32.512,1.458 32.512,2.947 33.747,4.181 35.53,4.181 38.368,7.019 38.368,13.271 38.06,13.58 34.808,13.58 34.276,14.112 32.45,14.112 32.21,13.872
NetR41_1 on Bottom Layer "BOTTOM_LAYER_NETR41_1_P378" (solid, pour order 378): 30.631,6.607 32.041,8.017 32.982,8.017 32.982,10.275 32.114,10.275 31.664,9.825 31.664,8.737 30.31,7.383 29.806,7.383 29.684,7.262 29.684,6.757 29.822,6.607
BIAS_ISO_GND1 on Bottom Layer "BOTTOM_LAYER_BIAS_ISO_GND1_P377" (solid, pour order 377): 31.242,10.4 31.436,10.594 33.104,10.594 33.271,10.426 33.271,6.882 30.256,3.866 30.256,1.412 30.4,1.268 31.052,1.268 31.229,1.445 31.242,1.445 31.242,2.521 31.245,2.524 31.245,3.5 33.209,5.464 34.865,5.464 35.783,6.382 35.783,10.932 33.846,12.869 32.071,12.869 31.763,13.177 31.763,13.975 33.211,15.423 33.211,18.814 32.993,19.032 31.664,19.032 31.477,18.845 31.477,17.942 31.482,15.655 31.117,15.29 30.545,15.29 29.056,13.801 29.056,8.847 29.425,8.477 30.918,8.477 31.242,8.802
XP4 on Bottom Layer "BOTTOM_LAYER_XP4_P374" (solid, pour order 374): 33.497,22.789 33.719,22.567 33.719,19.168 34.089,18.798 35.075,18.798 35.148,18.871 35.148,22.706 34.268,23.586 30.897,23.586 30.321,23.01 30.321,20.346 29.619,19.643 29.619,18.55 29.749,18.42 31.077,18.42 31.133,18.475 31.133,22.576 31.263,22.706 31.345,22.789 32.534,22.789
XP6 on Bottom Layer "BOTTOM_LAYER_XP6_P373" (solid, pour order 373): 27.461,18.459 27.29,18.63 27.29,22.59 29.282,24.582 36.317,24.582 37.751,23.148 37.751,19.316 37.734,19.256 37.242,18.764 36.567,18.764 36.062,19.268 36.062,22.622 34.804,23.88 30.816,23.88 29.97,23.034 29.97,20.663 28.967,19.66 28.967,19.032 28.318,18.459
PGND on Bottom Layer "BOTTOM_LAYER_PGND_P364" (solid, pour order 364): 36.223,32.396 38.5,32.396 38.547,32.443 38.547,35.089 36.352,35.089 36.23,34.967
BIAS_VIN on Bottom Layer "BOTTOM_LAYER_BIAS_VIN_P363" (solid, pour order 363): 24.262,32.319 23.876,31.933 23.876,29.868 24.262,29.482 37.959,29.482 38.547,30.069 38.547,31.987 36.508,31.987 36.491,32.004 35.689,31.203 33.188,31.203 32.766,31.625 32.766,33.508 32.734,33.508 32.473,33.77 31.504,33.77 31.242,33.508 31.242,31.375 31.023,31.156 27.723,31.156 27.17,31.708 27.17,32.331
XP3 on Bottom Layer "BOTTOM_LAYER_XP3_P362" (solid, pour order 362): 33.719,31.75 33.719,35.266 33.924,35.471 35.148,35.471 35.148,31.785 35.113,31.75
XP1 on Bottom Layer "BOTTOM_LAYER_XP1_P361" (solid, pour order 361): 28.623,31.75 28.623,35.145 28.886,35.409 30.423,35.409 30.423,31.75
PGND on Bottom Layer "BOTTOM_LAYER_PGND_P354" (solid, pour order 354): 10.68,1.003 10.68,1.886 11.092,2.298 12.671,2.298 12.671,2.356 13.483,3.168 13.483,4.602 13.485,4.602 14.018,5.135 16.473,5.135 17.272,4.337 17.272,1.003
PGND1 on Bottom Layer "BOTTOM_LAYER_PGND1_P253" (solid, remove dead copper, pour order 253): 8.634,1.014 6.082,1.014 6.082,7.96 6.552,8.43 10.278,8.43 10.579,8.129 10.579,4.641 8.634,2.696
PGND on Bottom Layer "BOTTOM_LAYER_PGND_P279" (solid, remove dead copper, pour order 279): 4.8,30.366 5.329,30.895 5.329,34.079 5.914,34.664 7.028,35.778 7.028,37.241 7.123,37.336 13.635,37.336 13.763,37.208 13.763,36.352 11.702,34.291 9.602,34.291 8.116,32.806 8.116,27.008 7.67,26.562 5.157,26.562 4.8,26.919
NetC63_1 on Bottom Layer "BOTTOM_LAYER_NETC63_1_P283" (solid, remove dead copper, pour order 283): 2.098,39.37 2.098,37.764 2.27,37.592 3.752,37.592 3.752,37.607 3.991,37.846 3.991,39.438 3.662,39.767 2.467,39.767
BIAS_VIN on Bottom Layer "BOTTOM_LAYER_BIAS_VIN_P281" (solid, remove dead copper, pour order 281): 14.015,37.846 6.79,37.846 6.239,37.295 6.239,36.258 5.014,35.052 1.524,35.052 1.27,35.332 1.27,37.255 1.432,37.417 4.084,37.417 4.318,37.651 4.318,39.513 4.683,39.878 13.971,39.878 14.263,39.586 14.263,38.094
NetC31_1 on Bottom Layer "BOTTOM_LAYER_NETC31_1_P277" (solid, remove dead copper, pour order 277): 4.203,30.571 4.683,31.051 4.683,33.128 4.394,33.416 0.904,33.416 0.508,33.02 0.508,27.064 0.915,26.562 3.965,26.562 4.203,26.799
PGND1 on Bottom Layer "BOTTOM_LAYER_PGND1_P275" (solid, remove dead copper, pour order 275): 4.946,17.777 7.878,17.777 8.191,18.09 8.191,24.828 7.944,25.075 5.11,25.075 4.635,24.6 4.635,18.088
BIAS_VIN_EMI on Bottom Layer "BOTTOM_LAYER_BIAS_VIN_EMI_P273" (solid, remove dead copper, pour order 273): 1.877,17.802 3.817,17.802 4.064,18.049 4.064,24.828 3.817,25.075 1.778,25.075 1.604,24.901 1.604,18.075
RTN1 on Bottom Layer "BOTTOM_LAYER_RTN1_P263" (solid, remove dead copper, pour order 263): 0.762,8.89 0.508,9.144 0.508,14.224 0.633,14.349 7.978,14.349 8.116,14.211 8.116,9.363 7.643,8.89
VBAT on Bottom Layer "BOTTOM_LAYER_VBAT_P255" (solid, remove dead copper, pour order 255): 4.826,1.005 4.826,7.925 4.321,8.43 0.809,8.43 0.508,8.129 0.508,1.333 0.825,1.016
PGND on Layer 2 "LAYER_2_PGND_P396" (solid, remove dead copper, pour order 396): 22.787,25.425 26.844,29.482 37.959,29.482 38.384,29.907 38.384,39.594 37.846,40.132 10.124,40.132 8.99,38.998 8.99,10.62 11.136,8.474 11.136,4.119 10.355,3.338 10.355,1.604 11.197,0.762 20.574,0.762 22.787,2.975
BIAS_12V on Layer 2 "LAYER_2_BIAS_12V_P134" (solid, remove dead copper, pour order 134): 14.976,23.748 14.976,20.387 13.846,19.256 12.964,19.256 12.733,19.488 12.733,20.82 14.202,22.288 14.202,23.529 14.46,23.787
BIAS_VIN on Layer 2 "LAYER_2_BIAS_VIN_P228" (solid, remove dead copper, pour order 228): 17.49,23.749 17.975,23.749 18.589,23.136 18.589,20.289 19.867,19.011 19.867,18.402 19.716,18.251 19.576,18.251 17.49,20.337
VBAT on Layer 2 "LAYER_2_VBAT_P393" (solid, remove dead copper, pour order 393): 5.26,7.996 4.826,8.43 0.809,8.43 0.5,8.129 0.5,3.563 1.01,3.053 4.739,3.053 5.26,3.574
RTN1 on Layer 2 "LAYER_2_RTN1_P394" (solid, remove dead copper, pour order 394): 0.508,10.532 0.508,9.144 0.762,8.89 5.623,8.89 6.841,10.109 6.841,16.157 6.248,16.75 0.881,16.75 0.508,16.377 0.508,14.413
PGND1 on Layer 2 "LAYER_2_PGND1_P337" (solid, remove dead copper, pour order 337): 10.278,8.43 8.543,10.165 8.543,18.956 8.228,19.271 6.731,19.271 6.452,18.991 6.452,17.639 7.209,16.882 7.209,9.833 5.637,8.302 5.637,3.563 6.147,3.053 8.807,3.053 10.593,4.839 10.593,8.115
BIAS_ISO_GND2 on Layer 2 "LAYER_2_BIAS_ISO_GND2_P333" (solid, pour order 333): 26.728,1.025 38.11,1.025 38.608,1.524 38.608,22.012 36.965,23.654 28.804,23.654 25.977,20.856 25.977,1.776
AGND1 on Layer 2 "LAYER_2_AGND1_P305" (solid, remove dead copper, pour order 305): 13.401,32.061 12.192,33.27 12.192,36.114 14.432,38.354 19.351,38.354 20.937,36.768 20.937,33.596 19.458,32.117
BIAS_VIN on Layer3 "LAYER3_BIAS_VIN_P178" (solid, remove dead copper, pour order 178): 22.032,11.961 23.873,13.802 23.873,24.853 27.175,28.155 27.175,32.358 26.974,32.559 25.689,32.559 25.266,32.136 25.266,28.59 22.564,25.887 21.72,25.887 21.472,25.639 21.472,24.795 22,24.268 22,14.505 21.633,14.139 19.873,14.139 19.535,13.801 19.535,12.04 19.615,11.961
BIAS_ISO_GND1 on Layer3 "LAYER3_BIAS_ISO_GND1_P390" (solid, pour order 390): 27.808,1.011 27.822,1.025 38.11,1.025 38.608,1.524 38.608,22.012 36.968,23.652 28.804,23.652 25.977,20.853 25.977,7.62 25.989,7.54 26.459,7.07 27.329,6.166 27.329,1.491
PGND on Layer3 "LAYER3_PGND_P353" (solid, remove dead copper, pour order 353): 21.764,23.947 21.18,24.53 21.18,25.758 21.539,26.117 22.358,26.117 25.723,29.482 37.959,29.482 38.384,29.907 38.384,39.594 37.846,40.132 10.124,40.132 8.99,38.998 8.99,10.62 11.136,8.474 11.136,4.119 10.355,3.338 10.355,1.604 11.197,0.762 20.574,0.762 21.764,1.952
PGND1 on Layer3 "LAYER3_PGND1_P287" (solid, remove dead copper, pour order 287): 10.593,8.115 10.278,8.43 6.078,8.43 5.637,8 5.637,3.66 6.244,3.053 8.807,3.053 10.593,4.839
VBAT on Layer3 "LAYER3_VBAT_P285" (solid, remove dead copper, pour order 285): 5.26,7.996 4.826,8.43 0.809,8.43 0.5,8.129 0.5,3.6 1.047,3.053 4.719,3.053 5.26,3.594
RTN1 on Layer3 "LAYER3_RTN1_P180" (solid, remove dead copper, pour order 180): 0.508,10.532 0.508,9.144 0.762,8.89 7.643,8.89 8.116,9.363 8.116,16.471 7.81,16.777 7.782,16.75 0.881,16.75 0.508,16.377 0.508,14.413
no net on Bottom Solder "NONET_L-01_P-001" (solid): 2.067,31.092 4.652,31.092 4.652,33.159 2.067,33.159
no net on Bottom Solder "NONET_L-01_P-001" (solid): 2.067,35.334 4.652,35.334 4.652,37.4 2.067,37.4

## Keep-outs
Keep-Out Layer:
  text ".Layer_Name" at 14.656,-21.806 h0.6

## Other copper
Top Layer:
  text ".Layer_Name" at 14.656,-21.806 h0.6
Bottom Layer:
  text ".Layer_Name" at 14.656,-21.806 h0.6

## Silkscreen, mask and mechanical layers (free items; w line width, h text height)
Top Overlay:
  text ".Layer_Name" at 14.656,-21.806 h0.6
Bottom Overlay:
  text "PMP41125B" at 27.159,4.736 h1
  text "Bias card" at 27.127,3.073 h1
  text "-5V" at 34.113,2.845 h0.71 r270
  text "COM" at 35.572,2.845 h0.71 r270
  text "12V" at 9.597,2.565 h0.71 r270
  text "5V" at 15.072,2.565 h0.71 r270
  text "-5V" at 28.992,2.565 h0.71 r270
  text "COM" at 30.423,2.565 h0.71 r270
  text "+12V" at 31.932,2.565 h0.71 r270
  text "+12V" at 36.856,2.565 h0.71 r270
  text "VIN+" at 3.159,2.235 h0.71 r270
  text "VIN-" at 6.985,2.235 h0.71 r270
  text ".Layer_Name" at 14.656,-21.806 h0.6
Top Paste:
  text ".Layer_Name" at 14.656,-21.806 h0.6
Bottom Paste:
  text ".Layer_Name" at 14.656,-21.806 h0.6
Top Solder:
  text ".Layer_Name" at 14.656,-21.806 h0.6
  text ".Layer_Name" at 14.656,-21.806 h0.6
Bottom Solder:
  text ".Layer_Name" at 14.656,-21.806 h0.6
Drill Guide:
  text ".Layer_Name" at 14.656,-21.806 h0.6
M1 Board Outline:
  the board outline again, w0.254
  text ".Layer_Name" at 14.656,-21.806 h0.6
M2 Board Dimensions:
  rectangle: 0,-6.985 3.175,-3.81
  rectangle: 3.175,-10.16 12.7,-6.985
  lines w0.178: 0,-6.985 25.4,-6.985 ; 3.175,-10.16 3.175,-3.81 ; 6.35,-10.16 6.35,-3.81 ; 12.7,-10.16 12.7,-3.81 ; 19.05,-10.16 19.05,-3.81 ; 0,-10.16 25.4,-10.16 25.4,-3.81 0,-3.81 0,-10.16
  text ".Layer_Name" at 14.656,-21.806 h0.6
M3 3D STEP Top:
  text ".Layer_Name" at 14.656,-21.806 h0.6
M4 3D STEP Bottom:
  text ".Layer_Name" at 14.656,-21.806 h0.6
Top M5 Assembly Top/M6 Assembly Bottom:
  lines w0.254: -7.417,-23.626 160.223,-23.626 ; -7.417,-18.462 160.274,-18.462 ; -7.417,-13.297 -7.417,-28.791 94.31,-28.791 160.274,-28.791 160.274,-13.297 -7.404,-13.297 -7.404,-28.791 32.614,-28.791 ; 55.194,-28.791 55.194,-13.297 ; 87.376,-18.462 87.376,-13.297 ; 108.712,-18.462 108.712,-13.297 ; 124.511,-28.956 124.511,-23.804
  text "COMPONENTS MARKED 'DNP' SHOULD NOT BE POPULATED." at 29.299,-8.09 h0.6
  text "ASSEMBLY VARIANT:" at 29.286,-11.024 h0.6
  text ".VariantName" at 55.601,-11.024 h0.6
  text "PCB VIEWED FROM TOP SIDE" at -5.804,-16.654 h0.6
  text "BOARD #:" at 57.099,-16.654 h0.6
  text ".PRJ_Number" at 70.955,-16.654 h0.6
  text "REV:" at 92.405,-16.654 h0.6
  text ".PCB_Rev" at 99.809,-16.654 h0.6
  text "SVN REV:" at 113.69,-16.654 h0.6
  text ".VersionControl_RevNumber" at 126.543,-16.654 h0.6
  text "TID #:" at 57.099,-21.819 h0.6
  text ".TID" at 70.955,-21.819 h0.6
  text "PLOT NAME =" at -5.804,-27.034 h0.6
  text ".plot_File_Name" at 14.656,-27.034 h0.6
  text "GENERATED    :" at 57.15,-27.034 h0.6
  text ".Print_Date" at 79.235,-27.034 h0.6
  text ".Print_Time" at 97.752,-27.034 h0.6
  text "TEXAS INSTRUMENTS" at 129.87,-27.034 h0.6
Bottom M5 Assembly Top/M6 Assembly Bottom:
  lines w0.254: -7.429,-18.474 160.261,-18.474 ; -7.379,-23.639 160.261,-23.639 ; 28.334,-28.969 28.334,-23.817 ; 44.133,-18.474 44.133,-13.31 ; 65.468,-18.474 65.468,-13.31 ; 97.65,-28.804 97.65,-13.31 ; 120.231,-28.804 160.249,-28.804 160.249,-13.31 -7.429,-13.31 -7.429,-28.804 58.534,-28.804 160.261,-28.804 160.261,-13.31
  text "COMPONENTS MARKED 'DNP' SHOULD NOT BE POPULATED." at 154.991,-8.077 h0.6
  text ".VariantName" at 128.473,-11.024 h0.6
  text "ASSEMBLY VARIANT:" at 154.864,-11.024 h0.6
  text ".VersionControl_RevNumber" at 26.302,-16.667 h0.6
  text "SVN REV:" at 39.154,-16.667 h0.6
  text ".PCB_Rev" at 53.035,-16.667 h0.6
  text "REV:" at 60.439,-16.667 h0.6
  text ".PRJ_Number" at 81.89,-16.667 h0.6
  text "BOARD #:" at 95.745,-16.667 h0.6
  text "PCB VIEWED FROM BOTTOM SIDE" at 158.648,-16.667 h0.6
  text ".TID" at 81.89,-21.831 h0.6
  text "TID #:" at 95.745,-21.831 h0.6
  text "TEXAS INSTRUMENTS" at 22.974,-27.047 h0.6
  text ".Print_Time" at 55.093,-27.047 h0.6
  text ".Print_Date" at 73.609,-27.047 h0.6
  text "GENERATED    :" at 95.694,-27.047 h0.6
  text ".plot_File_Name" at 138.189,-27.047 h0.6
  text "PLOT NAME =" at 158.648,-27.047 h0.6
M9 Title Sheet:
  drawing of 57 lines, arcs and shapes, not listed
  text "1" at 18.792,204.127 h1.78
  text "2" at 82.182,204.127 h1.78
  text "3" at 145.411,204.127 h1.78
  text "4" at 209.08,204.127 h1.78
  text "5" at 272.555,204.127 h1.78
  text "6" at 336.182,204.127 h1.78
  text "A" at -10.579,175.095 h1.78
  text "A" at 365.341,175.095 h1.78
  text "B" at -10.579,114.643 h1.78
  text "B" at 365.341,114.643 h1.78
  text "C" at -10.579,54.318 h1.78
  text "C" at 365.341,54.318 h1.78
  text "PROJECT TITLE:" at 288.125,7.048 h1.14
  text ".PRJ_Title" at 289.395,3.662 h1.78
  text "DESIGNED FOR:" at 288.125,-0.597 h1.14
  text ".PRJ_Customer" at 289.395,-4.153 h1.78
  text "D" at -10.579,-5.88 h1.78
  text "D" at 365.341,-5.88 h1.78
  text "FILE NAME:" at 288.125,-8.217 h1.14
  text ".PCB_File_Name_No_Path" at 289.395,-11.265 h1.78
  text "Texas Instruments (TI) and/or its licensors do not warrant the accuracy or completeness of this specification" at 161.9,-15.376 h1.14
  text "ENGINEER:" at 288.125,-15.583 h1.14
  text "LAYOUT BY:" at 326.352,-15.583 h1.14
  text "or any information contained therein. TI and/or its licensors do not warrant that this design will meet" at 160.757,-18.237 h1.14
  text ".PRJ_Engineer" at 289.395,-19.52 h1.78
  text ".PCB_Layout" at 327.635,-19.52 h1.78
  text "the specifications, will be suitable for your application or fit for any particular purpose, or will operate in" at 160.757,-21.099 h1.14
  text ".Layer_Name" at 14.656,-21.806 h0.6
  text "ALTIUM DESIGNER VERSION:" at 326.352,-23.457 h1.14
  text "an implementation. TI and/or its licensors do not warrant that the design is production worthy. You should" at 160.757,-23.961 h1.14
  text "completely validate and test your design implementation to confirm the system functionality for your application." at 161.9,-26.822 h1.14
  text ".print_Scale" at 289.395,-26.843 h1.78
  text ".Application_BuildNumber" at 327.635,-26.843 h1.78
  text "1" at 18.792,-32.093 h1.78
  text "2" at 82.182,-32.093 h1.78
  text "3" at 145.411,-32.093 h1.78
  text "4" at 209.08,-32.093 h1.78
  text "5" at 272.555,-32.093 h1.78
  text "6" at 336.182,-32.093 h1.78
M10 Fab Notes:
  drawing of 189 lines, arcs and shapes, not listed
  text "DESIGN INFORMATION" at 314.503,161.447 h0.6
  text "MIN. TRACK WIDTH:" at 298.131,158.091 h0.6
  text "8" at 325.976,158.091 h0.6
  text "MIL" at 329.907,158.091 h0.6
  text "7.874" at 321.75,155 h0.6
  text "MIN. CLEARANCE:" at 298.131,154.938 h0.6
  text "MIL" at 329.907,154.938 h0.6
  text "MIN. VIA PAD SIZE:" at 298.131,151.785 h0.6
  text "24" at 325.214,151.785 h0.6
  text "MIL" at 329.907,151.785 h0.6
  text "0.05mm (2MIL)" at 315.784,148.486 h0.6
  text "MINIMUM ANNULAR RING" at 289.769,148.277 h0.6
  text "EXTERNAL" at 333.768,148.277 h0.6
  text "PER" at 294.849,145.48 h0.6
  text "IPC-D-275 CLASS 2 LEVEL C" at 300.437,145.48 h0.6
  text "MIL, HOLES" at 338.238,142.928 h0.6
  text "+/-" at 328.27,142.709 h0.6
  text "+/-" at 349.961,142.709 h0.6
  text "REGISTRATION TOLERANCES:" at 289.769,142.682 h0.6
  text "METAL" at 320.243,142.682 h0.6
  text "5" at 334.879,142.683 h0.6
  text "3" at 356.037,142.683 h0.6
  text "MIL" at 358.99,142.682 h0.6
  text "HOLE SIZE TOLERANCE (UNLESS OTHERWISE SPECIFIED):" at 289.769,140.185 h0.6
  text "+/-" at 349.961,140.112 h0.6
  text "3" at 356.037,140.085 h0.6
  text "MIL" at 358.99,140.085 h0.6
  text "MATERIAL:" at 287.87,136.589 h0.6
  text "FR-4 High Tg" at 312.926,133.324 h0.6
  text "X" at 309.257,133.122 h0.6
  text "FR-4" at 298.563,133.007 h0.6
  text "OTHER" at 336.358,133.007 h0.6
  text "62 MIL (1.6mm) +/-10%" at 306.694,129.374 h0.6
  text "X" at 303.643,129.312 h0.6
  text "THICKNESS:" at 289.769,129.165 h0.6
  text "OTHER" at 339.33,129.165 h0.6
  text "TOLERANCE:" at 289.769,125.652 h0.6
  text "X" at 311.314,125.652 h0.6
  text "ANSI IPC-6012 TYPE 3 CLASS 2" at 315.836,125.652 h0.6
  text "OTHER +/-" at 315.835,121.989 h0.6
  text "BOW & TWIST:" at 289.769,118.302 h0.6
  text "X" at 311.314,118.302 h0.6
  text "ANSI IPC-6012 TYPE 3 CLASS 2" at 315.836,118.302 h0.6
  text "OTHER +/-" at 315.835,114.576 h0.6
  text "DRILLING:" at 287.87,111.258 h0.6
  text "NC_DRILL FILES" at 332.599,108.586 h0.6
  text "REFERENCE:" at 289.769,108.486 h0.6
  text "X" at 306.463,108.484 h0.6
  text "AS SHOWN" at 310.984,108.486 h0.6
  text "X" at 329.348,108.486 h0.6
  text "OTHER" at 340.168,104.873 h0.6
  text "PTH COPPER THICKNESS:" at 289.761,104.783 h0.6
  text "X" at 318.697,104.783 h0.6
  text "20-30 um" at 321.948,104.783 h0.6
  text "BOARD FINISH:" at 287.87,101.034 h0.6
  text "SILKSCREEN:" at 291.812,98.237 h0.6
  text "X" at 316.14,98.237 h0.6
  text "TOP" at 319.112,98.237 h0.6
  text "X" at 329.094,98.237 h0.6
  text "BOTTOM" at 332.091,98.237 h0.6
  text "SILKSCREEN COLOR:" at 291.812,94.295 h0.6
  text "X" at 316.115,94.295 h0.6
  text "WHITE" at 319.112,94.295 h0.6
  text "OTHER" at 332.091,94.295 h0.6
  text "X" at 319.442,90.652 h0.6
  text "GREEN" at 322.439,90.652 h0.6
  text "OTHER" at 338.136,90.652 h0.6
  text "SOLDER RESIST COLOR:" at 291.812,90.477 h0.6
  text "X" at 319.442,86.734 h0.6
  text "MATTE" at 322.439,86.734 h0.6
  text "SEMI-GLOSS" at 338.125,86.717 h0.6
  text "IMMERSION GOLD (ENIG)" at 314.819,82.345 h0.6
  text "ENEPIG" at 348.793,82.162 h0.6
  text "SURFACE FINISH:" at 287.87,82.136 h0.6
  text "X" at 310.298,82.136 h0.6
  text "IMM. TIN/SILVER OR EQUIV" at 296.24,78.649 h0.6
  text "OTHER" at 332.599,78.549 h0.6
  text "ARRAY/PANEL:" at 287.87,74.602 h0.6
  text "CUT AND TRIM PER M1 BOARD OUTLINE" at 314.819,74.393 h0.6
  text "N.C. ROUTE" at 314.819,70.94 h0.6
  text "X" at 332.295,70.94 h0.6
  text "V. SCORE" at 336.816,70.94 h0.6
  text "CERTIFICATION:" at 287.87,67.66 h0.6
  text "MATERIALS AND WORKMANSHIP FOR ALL PCBS" at 306.285,67.66 h0.6
  text "TO MEET OR EXCEED THE REQUIREMENTS OF:" at 306.285,65.271 h0.6
  text "X" at 297.078,62.003 h0.6
  text "ANSI IPC-A-600F CLASS ->" at 300.329,62.003 h0.6
  text "X" at 342.188,62.003 h0.6
  text "2" at 344.982,62.003 h0.6
  text "1" at 336.981,61.965 h0.6
  text "3" at 353.973,61.965 h0.6
  text "X" at 317.702,58.252 h0.6
  text "RoHS" at 320.953,58.252 h0.6
  text "OTHER" at 337.321,58.252 h0.6
  text "PER ORDER" at 347.407,58.252 h0.6
  text "ALL BOARDS MUST MEET OR EXCEED UL94-V0 REQUIREMENTS." at 288.569,54.345 h0.6
  text "PCB MUST BEAR THE UL94V-0 UL REGISTERED MATERIAL ID NUMBER" at 288.569,51.397 h0.6
  text "ADDITIONAL REQUIREMENTS:" at 287.87,47.094 h0.6
  text "MICROSECTION:" at 289.769,44.373 h0.6
  text "YES" at 312.775,44.373 h0.6
  text "REQUIRED" at 334.657,40.707 h0.6
  text "BARE BOARD ELEC. TEST:" at 289.769,40.634 h0.6
  text "NONE" at 322.935,40.634 h0.6
  text "X" at 331.66,40.634 h0.6
  text "PER ORDER" at 349.693,40.634 h0.6
  text "XX MIL VIAS REQUIRE NON-CONDUCTIVE FILL AND PLANARIZE" at 294.04,35.428 h1.5
  text "XX MIL VIAS REQUIRE CONDUCTIVE FILL AND PLANARIZE" at 294.243,32.787 h0.6
  text "OUTER XX MIL TRACES REQUIRE 50 OHM SINGLE-ENDED IMPEDANCE" at 294.218,28.637 h1.47
  text "LAYER 2 & 3 (INNER LAYERS) XX MIL WIDE, XX MIL SPACE / TRACES REQUIRE 100 OHM DIFFERENTIAL IMPEDANCE" at 294.015,22.65 h0.6
  text ".Layer_Name" at 14.656,-21.806 h0.6
M11 Gerber Information:
  lines w0.254: -7.417,-23.626 160.223,-23.626 ; -7.417,-18.462 160.274,-18.462 ; -7.417,-13.297 -7.417,-28.791 94.31,-28.791 160.274,-28.791 160.274,-13.297 -7.404,-13.297 -7.404,-28.791 32.614,-28.791 ; 55.194,-28.791 55.194,-13.297 ; 87.376,-18.462 87.376,-13.297 ; 108.712,-18.462 108.712,-13.297 ; 124.511,-28.956 124.511,-23.804
  text "ALL ARTWORK VIEWED FROM TOP SIDE" at -5.804,-16.654 h0.6
  text "BOARD #:" at 57.099,-16.654 h0.6
  text ".PRJ_Number" at 70.955,-16.654 h0.6
  text "REV:" at 92.405,-16.654 h0.6
  text ".PCB_Rev" at 99.809,-16.654 h0.6
  text "SVN REV:" at 113.69,-16.654 h0.6
  text ".VersionControl_RevNumber" at 126.543,-16.654 h0.6
  text "LAYER NAME =" at -5.804,-21.806 h0.6
  text "TID #:" at 57.099,-21.819 h0.6
  text ".TID" at 70.955,-21.819 h0.6
  text "PLOT NAME =" at -5.804,-27.034 h0.6
  text ".plot_File_Name" at 14.656,-27.034 h0.6
  text "GENERATED    :" at 57.15,-27.034 h0.6
  text ".Print_Date" at 79.235,-27.034 h0.6
  text ".Print_Time" at 97.752,-27.034 h0.6
  text "TEXAS INSTRUMENTS" at 129.87,-27.034 h0.6
M12 Stackup:
  drawing of 306 lines, arcs and shapes, not listed
  text "Layer" at 248.544,186.551 h0.6
  text "Name" at 252.952,186.551 h0.6
  text "Material" at 262.557,186.551 h0.6
  text "Thickness" at 271.463,186.551 h0.6
  text "Constant" at 278.269,186.551 h0.6
  text "Board Layer Stack" at 284.276,186.551 h0.6
  text "Top Overlay" at 252.952,185.351 h0.6
  text "Top Solder" at 252.952,184.151 h0.6
  text "Solder Resist" at 262.557,184.151 h0.6
  text "0.40mil" at 271.463,184.151 h0.6
  text "3.5" at 278.269,184.151 h0.6
  text "1" at 248.544,182.951 h0.6
  text "Top Layer" at 252.952,182.951 h0.6
  text "2.76mil" at 271.463,182.951 h0.6
  text "Dielectric1" at 252.952,181.751 h0.6
  text "5.00mil" at 271.463,181.751 h0.6
  text "4.2" at 278.269,181.751 h0.6
  text "2" at 248.544,180.551 h0.6
  text "Layer 2" at 252.952,180.551 h0.6
  text "2.76mil" at 271.463,180.551 h0.6
  text "Dielectric 3" at 252.952,179.351 h0.6
  text "5.00mil" at 271.463,179.351 h0.6
  text "4.2" at 278.269,179.351 h0.6
  text "3" at 248.544,178.151 h0.6
  text "Layer3" at 252.952,178.151 h0.6
  text "2.76mil" at 271.463,178.151 h0.6
  text "Dielectric 5" at 252.952,176.951 h0.6
  text "5.00mil" at 271.463,176.951 h0.6
  text "4.2" at 278.269,176.951 h0.6
  text "4" at 248.544,175.751 h0.6
  text "Bottom Layer" at 252.952,175.751 h0.6
  text "2.76mil" at 271.463,175.751 h0.6
  text "Bottom Solder" at 252.952,174.551 h0.6
  text "Solder Resist" at 262.557,174.551 h0.6
  text "0.40mil" at 271.463,174.551 h0.6
  text "3.5" at 278.269,174.551 h0.6
  text "Bottom Overlay" at 252.952,173.351 h0.6
  text ".Layer_Name" at 14.656,-21.806 h0.6
M13 Component Bodies Top:
  text ".Layer_Name" at 14.656,-21.806 h0.6
M14 Component Bodies Bottom:
  text ".Layer_Name" at 14.656,-21.806 h0.6
M15 Courtyards Top:
  text ".Layer_Name" at 14.656,-21.806 h0.6
M16 Courtyards Bottom:
  text ".Layer_Name" at 14.656,-21.806 h0.6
